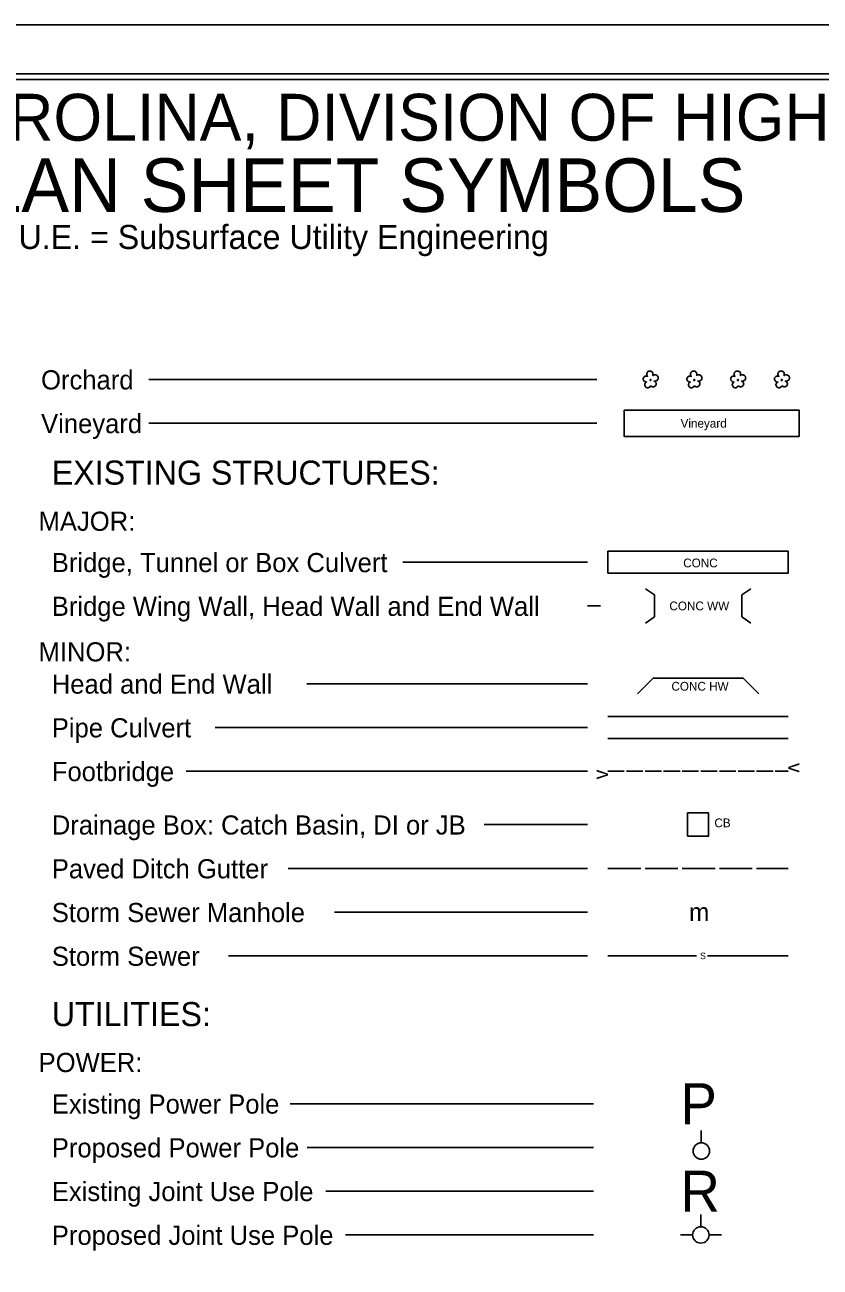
# Model space of a CAD drawing. Extents: x 1729679 to 1731363, y 539860 to 540960.
# Drawn here: x 1730602 to 1730965, y 540392 to 540960 of the extents above; entities that cross this region are included whole.
import ezdxf

# ---------------------------------------------------------------- set-up
doc = ezdxf.new("R2010")
doc.units = 0
for name, color, linetype in [('Sheet Plot Border Inside CELL', 7, 'Continuous'), ('Sheet Plot Border Outside CELL', 7, 'Continuous'), ('Sheet Symbology CELL', 7, 'Continuous')]:
    doc.layers.add(name, color=color, linetype=linetype)

msp = doc.modelspace()

# ---------------------------------------------------------------- linework, layer by layer
at = {"layer": 'Sheet Plot Border Inside CELL'}
msp.add_lwpolyline([(1729692.08, 539882.79), (1731358.58, 539882.79), (1731358.58, 540937.89), (1729692.08, 540937.89)], close=True, dxfattribs=at)
at = {"layer": 'Sheet Plot Border Outside CELL'}
msp.add_lwpolyline([(1729679.08, 539860.34), (1731363.08, 539860.34), (1731363.08, 540960.34), (1729679.08, 540960.34)], close=True, dxfattribs=at)
at = {"layer": 'Sheet Symbology CELL'}
for p, q in [((1730863.41, 540798.17), (1730658.47, 540798.17)), ((1730863.41, 540778.17), (1730658.47, 540778.17)), ((1730859.09, 540714.66), (1730774.67, 540714.66)), ((1730885.54, 540702.53), (1730889.64, 540699.66)), ((1730889.64, 540699.66), (1730889.64, 540689.66)), ((1730933.74, 540702.53), (1730929.64, 540699.66)), ((1730929.64, 540699.66), (1730929.64, 540689.66)), ((1730859.09, 540694.66), (1730865.08, 540694.66)), ((1730885.54, 540686.8), (1730889.64, 540689.66)), ((1730933.74, 540686.8), (1730929.64, 540689.66)), ((1730859.09, 540659.1), (1730730.79, 540659.1)), ((1730881.94, 540654.52), (1730889.02, 540661.6)), ((1730889.02, 540661.6), (1730930.27, 540661.6)), ((1730930.27, 540661.6), (1730937.34, 540654.52)), ((1730868.39, 540644.1), (1730950.89, 540644.1)), ((1730859.09, 540639.1), (1730688.9, 540639.1)), ((1730868.39, 540634.1), (1730950.89, 540634.1)), ((1730859.09, 540619.1), (1730675.62, 540619.1)), ((1730868.39, 540619.1), (1730875.89, 540619.1)), ((1730876.89, 540619.1), (1730884.39, 540619.1)), ((1730885.39, 540619.1), (1730892.89, 540619.1)), ((1730893.89, 540619.1), (1730901.39, 540619.1)), ((1730902.39, 540619.1), (1730909.89, 540619.1)), ((1730910.89, 540619.1), (1730918.39, 540619.1)), ((1730919.39, 540619.1), (1730926.89, 540619.1)), ((1730927.89, 540619.1), (1730935.39, 540619.1)), ((1730936.39, 540619.1), (1730943.89, 540619.1)), ((1730944.89, 540619.1), (1730950.89, 540619.1)), ((1730859.09, 540594.66), (1730811.89, 540594.66)), ((1730859.09, 540574.66), (1730722.14, 540574.66)), ((1730868.39, 540574.66), (1730883.39, 540574.66)), ((1730885.39, 540574.66), (1730900.39, 540574.66)), ((1730902.39, 540574.66), (1730917.39, 540574.66)), ((1730919.39, 540574.66), (1730934.39, 540574.66)), ((1730936.39, 540574.66), (1730950.89, 540574.66)), ((1730859.09, 540554.66), (1730743.42, 540554.66)), ((1730859.09, 540534.66), (1730694.89, 540534.66)), ((1730868.39, 540534.66), (1730908.92, 540534.66)), ((1730913.92, 540534.66), (1730950.89, 540534.66)), ((1730861.88, 540467.08), (1730723.18, 540467.08)), ((1730911.1, 540449.19), (1730911.1, 540454.82)), ((1730861.88, 540447.08), (1730730.97, 540447.08)), ((1730861.88, 540427.08), (1730739.37, 540427.08)), ((1730910.89, 540410.84), (1730910.89, 540416.47)), ((1730861.88, 540407.08), (1730748.37, 540407.08)), ((1730907.14, 540407.09), (1730901.52, 540407.09)), ((1730914.64, 540407.09), (1730920.27, 540407.09))]:
    msp.add_line(p, q, dxfattribs=at)
for points in [[(1731346.08, 540935.34), (1729846.08, 540935.34), (1729846.08, 539886.35), (1731346.08, 539886.35)], [(1730904.83, 540589.35), (1730914.44, 540589.35), (1730914.44, 540599.99), (1730904.83, 540599.99)]]:
    msp.add_lwpolyline(points, close=True, dxfattribs=at)
for points in [[(1730888.85, 540799.92), (1730889, 540800.22), (1730889.05, 540800.52), (1730889, 540800.82), (1730888.95, 540801.12), (1730888.8, 540801.37), (1730888.65, 540801.62), (1730888.4, 540801.82), (1730888.15, 540801.97), (1730887.8, 540802.07), (1730887.55, 540802.07), (1730887.25, 540802.02), (1730886.95, 540801.92), (1730886.7, 540801.77), (1730886.45, 540801.57), (1730886.3, 540801.27), (1730886.2, 540801.02), (1730886.15, 540800.72), (1730886.15, 540800.42), (1730886.2, 540800.12), (1730886.35, 540799.87), (1730886.55, 540799.57), (1730886.3, 540799.72), (1730886, 540799.77), (1730885.7, 540799.77), (1730885.45, 540799.67), (1730885.2, 540799.57), (1730884.95, 540799.37), (1730884.75, 540799.17), (1730884.6, 540798.92), (1730884.55, 540798.67), (1730884.5, 540798.32), (1730884.55, 540798.07), (1730884.65, 540797.82), (1730884.85, 540797.57), (1730885, 540797.37), (1730885.25, 540797.22), (1730885.55, 540797.07), (1730885.8, 540797.02), (1730886.1, 540797.02), (1730885.85, 540796.92), (1730885.6, 540796.72), (1730885.45, 540796.52), (1730885.35, 540796.22), (1730885.25, 540795.92), (1730885.25, 540795.67), (1730885.3, 540795.37), (1730885.45, 540795.12), (1730885.6, 540794.87), (1730885.8, 540794.67), (1730886.05, 540794.52), (1730886.3, 540794.42), (1730886.6, 540794.42), (1730886.9, 540794.42), (1730887.15, 540794.47), (1730887.4, 540794.67), (1730887.65, 540794.82), (1730887.9, 540795.27)], [(1730908.85, 540799.92), (1730909, 540800.22), (1730909.05, 540800.52), (1730909, 540800.82), (1730908.95, 540801.12), (1730908.8, 540801.37), (1730908.65, 540801.62), (1730908.4, 540801.82), (1730908.15, 540801.97), (1730907.8, 540802.07), (1730907.55, 540802.07), (1730907.25, 540802.02), (1730906.95, 540801.92), (1730906.7, 540801.77), (1730906.45, 540801.57), (1730906.3, 540801.27), (1730906.2, 540801.02), (1730906.15, 540800.72), (1730906.15, 540800.42), (1730906.2, 540800.12), (1730906.35, 540799.87), (1730906.55, 540799.57), (1730906.3, 540799.72), (1730906, 540799.77), (1730905.7, 540799.77), (1730905.45, 540799.67), (1730905.2, 540799.57), (1730904.95, 540799.37), (1730904.75, 540799.17), (1730904.6, 540798.92), (1730904.55, 540798.67), (1730904.5, 540798.32), (1730904.55, 540798.07), (1730904.65, 540797.82), (1730904.85, 540797.57), (1730905, 540797.37), (1730905.25, 540797.22), (1730905.55, 540797.07), (1730905.8, 540797.02), (1730906.1, 540797.02), (1730905.85, 540796.92), (1730905.6, 540796.72), (1730905.45, 540796.52), (1730905.35, 540796.22), (1730905.25, 540795.92), (1730905.25, 540795.67), (1730905.3, 540795.37), (1730905.45, 540795.12), (1730905.6, 540794.87), (1730905.8, 540794.67), (1730906.05, 540794.52), (1730906.3, 540794.42), (1730906.6, 540794.42), (1730906.9, 540794.42), (1730907.15, 540794.47), (1730907.4, 540794.67), (1730907.65, 540794.82), (1730907.9, 540795.27)], [(1730928.85, 540799.92), (1730929, 540800.22), (1730929.05, 540800.52), (1730929, 540800.82), (1730928.95, 540801.12), (1730928.8, 540801.37), (1730928.65, 540801.62), (1730928.4, 540801.82), (1730928.15, 540801.97), (1730927.8, 540802.07), (1730927.55, 540802.07), (1730927.25, 540802.02), (1730926.95, 540801.92), (1730926.7, 540801.77), (1730926.45, 540801.57), (1730926.3, 540801.27), (1730926.2, 540801.02), (1730926.15, 540800.72), (1730926.15, 540800.42), (1730926.2, 540800.12), (1730926.35, 540799.87), (1730926.55, 540799.57), (1730926.3, 540799.72), (1730926, 540799.77), (1730925.7, 540799.77), (1730925.45, 540799.67), (1730925.2, 540799.57), (1730924.95, 540799.37), (1730924.75, 540799.17), (1730924.6, 540798.92), (1730924.55, 540798.67), (1730924.5, 540798.32), (1730924.55, 540798.07), (1730924.65, 540797.82), (1730924.85, 540797.57), (1730925, 540797.37), (1730925.25, 540797.22), (1730925.55, 540797.07), (1730925.8, 540797.02), (1730926.1, 540797.02), (1730925.85, 540796.92), (1730925.6, 540796.72), (1730925.45, 540796.52), (1730925.35, 540796.22), (1730925.25, 540795.92), (1730925.25, 540795.67), (1730925.3, 540795.37), (1730925.45, 540795.12), (1730925.6, 540794.87), (1730925.8, 540794.67), (1730926.05, 540794.52), (1730926.3, 540794.42), (1730926.6, 540794.42), (1730926.9, 540794.42), (1730927.15, 540794.47), (1730927.4, 540794.67), (1730927.65, 540794.82), (1730927.9, 540795.27)], [(1730948.85, 540799.92), (1730949, 540800.22), (1730949.05, 540800.52), (1730949, 540800.82), (1730948.95, 540801.12), (1730948.8, 540801.37), (1730948.65, 540801.62), (1730948.4, 540801.82), (1730948.15, 540801.97), (1730947.8, 540802.07), (1730947.55, 540802.07), (1730947.25, 540802.02), (1730946.95, 540801.92), (1730946.7, 540801.77), (1730946.45, 540801.57), (1730946.3, 540801.27), (1730946.2, 540801.02), (1730946.15, 540800.72), (1730946.15, 540800.42), (1730946.2, 540800.12), (1730946.35, 540799.87), (1730946.55, 540799.57), (1730946.3, 540799.72), (1730946, 540799.77), (1730945.7, 540799.77), (1730945.45, 540799.67), (1730945.2, 540799.57), (1730944.95, 540799.37), (1730944.75, 540799.17), (1730944.6, 540798.92), (1730944.55, 540798.67), (1730944.5, 540798.32), (1730944.55, 540798.07), (1730944.65, 540797.82), (1730944.85, 540797.57), (1730945, 540797.37), (1730945.25, 540797.22), (1730945.55, 540797.07), (1730945.8, 540797.02), (1730946.1, 540797.02), (1730945.85, 540796.92), (1730945.6, 540796.72), (1730945.45, 540796.52), (1730945.35, 540796.22), (1730945.25, 540795.92), (1730945.25, 540795.67), (1730945.3, 540795.37), (1730945.45, 540795.12), (1730945.6, 540794.87), (1730945.8, 540794.67), (1730946.05, 540794.52), (1730946.3, 540794.42), (1730946.6, 540794.42), (1730946.9, 540794.42), (1730947.15, 540794.47), (1730947.4, 540794.67), (1730947.65, 540794.82), (1730947.9, 540795.27)], [(1730888, 540798.17), (1730887.85, 540798.17), (1730887.75, 540798.12), (1730887.65, 540798.07), (1730887.65, 540797.92), (1730887.65, 540797.82), (1730887.75, 540797.72), (1730887.9, 540797.72), (1730888, 540797.72), (1730888.1, 540797.82), (1730888.15, 540797.97), (1730888.1, 540798.07), (1730888, 540798.17)], [(1730887.9, 540795.27), (1730888.5, 540794.92), (1730888.8, 540794.82), (1730889.1, 540794.77), (1730889.4, 540794.82), (1730889.65, 540794.92), (1730889.9, 540795.07), (1730890.15, 540795.27), (1730890.3, 540795.52), (1730890.4, 540795.77), (1730890.5, 540796.07), (1730890.45, 540796.37), (1730890.4, 540796.67), (1730890.2, 540796.97), (1730890.05, 540797.17), (1730889.8, 540797.32), (1730889.5, 540797.47), (1730889.8, 540797.42), (1730890.15, 540797.42), (1730890.4, 540797.52), (1730890.7, 540797.67), (1730890.95, 540797.82), (1730891.15, 540798.07), (1730891.3, 540798.37), (1730891.35, 540798.67), (1730891.4, 540798.97), (1730891.35, 540799.27), (1730891.25, 540799.57), (1730891.05, 540799.82), (1730890.8, 540800.07), (1730890.55, 540800.22), (1730890.25, 540800.32), (1730889.95, 540800.37), (1730889.65, 540800.37), (1730889.35, 540800.27), (1730889.1, 540800.12), (1730888.85, 540799.92)], [(1730908, 540798.17), (1730907.85, 540798.17), (1730907.75, 540798.12), (1730907.65, 540798.07), (1730907.65, 540797.92), (1730907.65, 540797.82), (1730907.75, 540797.72), (1730907.9, 540797.72), (1730908, 540797.72), (1730908.1, 540797.82), (1730908.15, 540797.97), (1730908.1, 540798.07), (1730908, 540798.17)], [(1730907.9, 540795.27), (1730908.5, 540794.92), (1730908.8, 540794.82), (1730909.1, 540794.77), (1730909.4, 540794.82), (1730909.65, 540794.92), (1730909.9, 540795.07), (1730910.15, 540795.27), (1730910.3, 540795.52), (1730910.4, 540795.77), (1730910.5, 540796.07), (1730910.45, 540796.37), (1730910.4, 540796.67), (1730910.2, 540796.97), (1730910.05, 540797.17), (1730909.8, 540797.32), (1730909.5, 540797.47), (1730909.8, 540797.42), (1730910.15, 540797.42), (1730910.4, 540797.52), (1730910.7, 540797.67), (1730910.95, 540797.82), (1730911.15, 540798.07), (1730911.3, 540798.37), (1730911.35, 540798.67), (1730911.4, 540798.97), (1730911.35, 540799.27), (1730911.25, 540799.57), (1730911.05, 540799.82), (1730910.8, 540800.07), (1730910.55, 540800.22), (1730910.25, 540800.32), (1730909.95, 540800.37), (1730909.65, 540800.37), (1730909.35, 540800.27), (1730909.1, 540800.12), (1730908.85, 540799.92)], [(1730928, 540798.17), (1730927.85, 540798.17), (1730927.75, 540798.12), (1730927.65, 540798.07), (1730927.65, 540797.92), (1730927.65, 540797.82), (1730927.75, 540797.72), (1730927.9, 540797.72), (1730928, 540797.72), (1730928.1, 540797.82), (1730928.15, 540797.97), (1730928.1, 540798.07), (1730928, 540798.17)], [(1730927.9, 540795.27), (1730928.5, 540794.92), (1730928.8, 540794.82), (1730929.1, 540794.77), (1730929.4, 540794.82), (1730929.65, 540794.92), (1730929.9, 540795.07), (1730930.15, 540795.27), (1730930.3, 540795.52), (1730930.4, 540795.77), (1730930.5, 540796.07), (1730930.45, 540796.37), (1730930.4, 540796.67), (1730930.2, 540796.97), (1730930.05, 540797.17), (1730929.8, 540797.32), (1730929.5, 540797.47), (1730929.8, 540797.42), (1730930.15, 540797.42), (1730930.4, 540797.52), (1730930.7, 540797.67), (1730930.95, 540797.82), (1730931.15, 540798.07), (1730931.3, 540798.37), (1730931.35, 540798.67), (1730931.4, 540798.97), (1730931.35, 540799.27), (1730931.25, 540799.57), (1730931.05, 540799.82), (1730930.8, 540800.07), (1730930.55, 540800.22), (1730930.25, 540800.32), (1730929.95, 540800.37), (1730929.65, 540800.37), (1730929.35, 540800.27), (1730929.1, 540800.12), (1730928.85, 540799.92)], [(1730948, 540798.17), (1730947.85, 540798.17), (1730947.75, 540798.12), (1730947.65, 540798.07), (1730947.65, 540797.92), (1730947.65, 540797.82), (1730947.75, 540797.72), (1730947.9, 540797.72), (1730948, 540797.72), (1730948.1, 540797.82), (1730948.15, 540797.97), (1730948.1, 540798.07), (1730948, 540798.17)], [(1730947.9, 540795.27), (1730948.5, 540794.92), (1730948.8, 540794.82), (1730949.1, 540794.77), (1730949.4, 540794.82), (1730949.65, 540794.92), (1730949.9, 540795.07), (1730950.15, 540795.27), (1730950.3, 540795.52), (1730950.4, 540795.77), (1730950.5, 540796.07), (1730950.45, 540796.37), (1730950.4, 540796.67), (1730950.2, 540796.97), (1730950.05, 540797.17), (1730949.8, 540797.32), (1730949.5, 540797.47), (1730949.8, 540797.42), (1730950.15, 540797.42), (1730950.4, 540797.52), (1730950.7, 540797.67), (1730950.95, 540797.82), (1730951.15, 540798.07), (1730951.3, 540798.37), (1730951.35, 540798.67), (1730951.4, 540798.97), (1730951.35, 540799.27), (1730951.25, 540799.57), (1730951.05, 540799.82), (1730950.8, 540800.07), (1730950.55, 540800.22), (1730950.25, 540800.32), (1730949.95, 540800.37), (1730949.65, 540800.37), (1730949.35, 540800.27), (1730949.1, 540800.12), (1730948.85, 540799.92)], [(1730875.8, 540784.17), (1730955.8, 540784.17), (1730955.8, 540772.17), (1730875.8, 540772.17), (1730875.8, 540784.17)], [(1730868.39, 540719.66), (1730950.89, 540719.66), (1730950.89, 540709.66), (1730868.39, 540709.66), (1730868.39, 540719.66)]]:
    msp.add_lwpolyline(points, dxfattribs=at)
for centre in [(1730911.1, 540445.44), (1730910.89, 540407.08)]:
    msp.add_circle(centre, 3.75, dxfattribs=at)

# ---------------------------------------------------------------- texts
for s, height, p in [('STATE OF NORTH CAROLINA, DIVISION OF HIGHWAYS', 21.419, (1730296.64, 540907.38)), ('CONVENTIONAL  PLAN SHEET SYMBOLS', 24.4803, (1730283.69, 540874.81)), ('Orchard', 8.75, (1730609.24, 540793.65)), ('Vineyard', 8.75, (1730609.24, 540773.65)), ('EXISTING STRUCTURES:', 11, (1730614.13, 540750.11)), ('MAJOR:', 8.75, (1730608.1, 540729)), ('Bridge, Tunnel or Box Culvert', 8.75, (1730614.13, 540710.11)), ('CONC', 4, (1730902.83, 540712.3)), ('Bridge Wing Wall, Head Wall and End Wall', 8.75, (1730614.13, 540690.11)), ('MINOR:', 8.75, (1730608.1, 540669.3)), ('Head and End Wall', 8.75, (1730614.13, 540654.55)), ('Pipe Culvert', 8.75, (1730614.13, 540634.56)), ('Footbridge', 8.75, (1730614.14, 540614.56)), ('Drainage Box: Catch Basin, DI or JB', 8.75, (1730614.14, 540590.13)), ('Paved Ditch Gutter', 8.75, (1730614.14, 540570.11)), ('Storm Sewer Manhole', 8.75, (1730614.14, 540550.11)), ('m', 8.25, (1730905.52, 540550.54)), ('Storm Sewer', 8.75, (1730614.14, 540530.11)), ('S', 3, (1730910.52, 540533.16)), ('UTILITIES:', 11, (1730614.13, 540502.53)), ('POWER:', 8.75, (1730608.1, 540481.54)), ('Existing Power Pole', 8.75, (1730614.14, 540462.54)), ('P', 18.75, (1730901.52, 540457.7)), ('Proposed Power Pole', 8.75, (1730614.14, 540442.54)), ('Existing Joint Use Pole', 8.75, (1730614.14, 540422.55)), ('R', 18.75, (1730901.52, 540417.7)), ('Proposed Joint Use Pole', 8.75, (1730614.15, 540402.54))]:
    msp.add_text(s, height=height, dxfattribs=at).set_placement(p)
for s, height, rotation, p in [('*S.U.E. = Subsurface Utility Engineering', 11, 360, (1730579.3, 540857.85)), ('Vineyard', 4, 0, (1730901.62, 540776.17)), ('CONC WW', 4, 0, (1730896.52, 540692.66)), ('CONC HW', 4, 360, (1730897.44, 540655.93)), ('v', 6.6, 89.7591, (1730868.38, 540615.36)), ('v', 6.6, 270.2409, (1730950.88, 540622.83)), ('CB', 4, 360, (1730917.08, 540593.49))]:
    msp.add_text(s, height=height, rotation=rotation, dxfattribs=at).set_placement(p)

doc.saveas('drawing.dxf')
